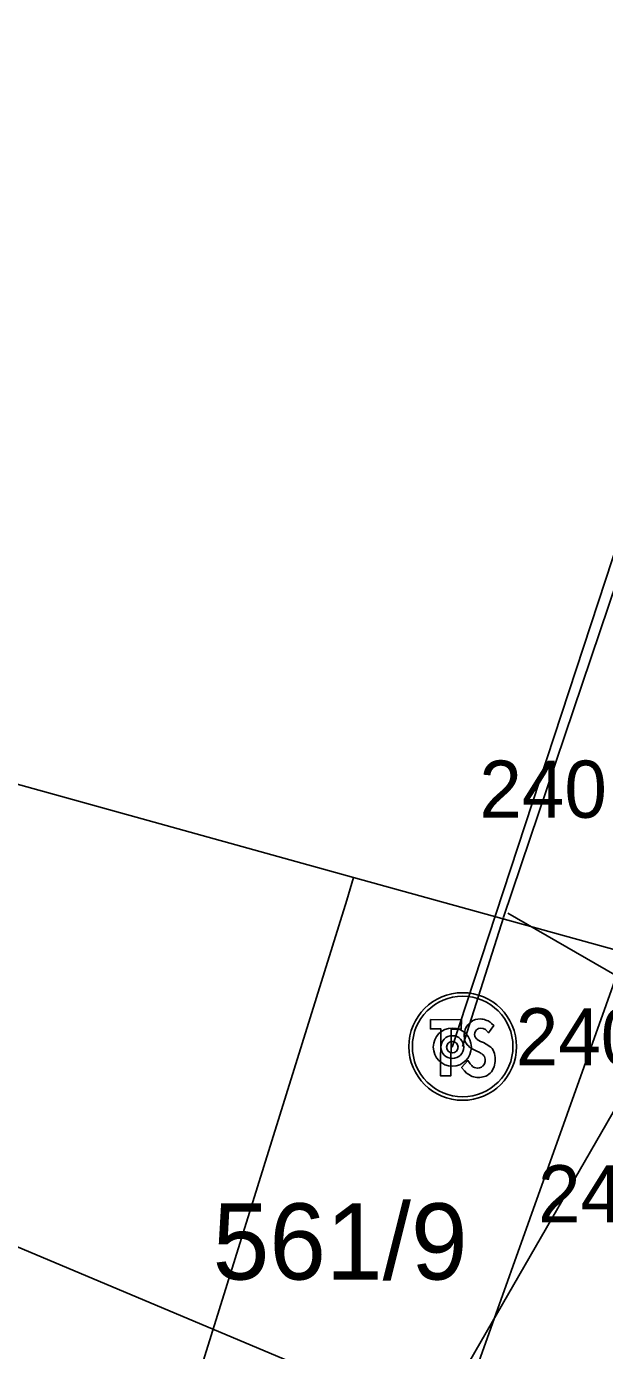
# Model space of a CAD drawing. Extents: x -555757 to -553364, y -1100723 to -1096439.
# Drawn here: x -553996.25 to -553981.08, y -1099139.41 to -1099104.66 of the extents above; entities that cross this region are included whole.
import ezdxf

# ---------------------------------------------------------------- set-up
doc = ezdxf.new("R2010")
doc.units = 0
for name, color, linetype in [('00_NÁVRH - 0.35 mm', 7, 'Continuous'), ('00_NÁVRH - Řezy', 7, 'Continuous'), ('01_HLADINA', 7, 'Continuous'), ('05_SÍTĚ - vedení VN - nadzemní', 7, 'Continuous'), ('C$SLO$PARCELY', 7, 'Continuous'), ('HRANICE$PARCELY', 7, 'Continuous'), ('PLOTY', 7, 'Continuous'), ('SLOUPY', 7, 'Continuous'), ('Stanice', 7, 'Continuous'), ('VCHOD', 7, 'Continuous'), ('VYSKA_PODR_BOD', 7, 'Continuous')]:
    doc.layers.add(name, color=color, linetype=linetype)

# ---------------------------------------------------------------- blocks, each defined once
blk = doc.blocks.new('6$01')
at = {"layer": 'SLOUPY'}
for radius in [0.5, 0.3, 0.15]:
    blk.add_circle((0, 0), radius, dxfattribs=at)
blk = doc.blocks.new('DGN_COMPLEXSHAPE')
at = {"layer": 'Stanice'}
for p, q in [((-553984.585, -1099130.792), (-553984.585, -1099130.792)), ((-553984.331, -1099130.711), (-553984.331, -1099130.711)), ((-553984.755, -1099131.19), (-553984.755, -1099131.19)), ((-553984.481, -1099131.16), (-553984.481, -1099131.16)), ((-553984.436, -1099130.998), (-553984.436, -1099130.998)), ((-553984.203, -1099130.991), (-553984.203, -1099130.991)), ((-553984.742, -1099131.264), (-553984.742, -1099131.264)), ((-553984.648, -1099131.419), (-553984.648, -1099131.419)), ((-553984.513, -1099131.515), (-553984.513, -1099131.515)), ((-553984.414, -1099131.249), (-553984.414, -1099131.249)), ((-553984.181, -1099131.371), (-553984.181, -1099131.371)), ((-553984.028, -1099131.489), (-553984.028, -1099131.489)), ((-553984.309, -1099131.615), (-553984.309, -1099131.615)), ((-553984.228, -1099131.7), (-553984.228, -1099131.7)), ((-553984.466, -1099132.24), (-553984.466, -1099132.24)), ((-553984.456, -1099131.993), (-553984.456, -1099131.993)), ((-553984.266, -1099131.946), (-553984.266, -1099131.946))]:
    blk.add_line(p, q, dxfattribs=at)
for points in [[(-553984.203, -1099130.991), (-553984.12, -1099131.075), (-553983.982, -1099130.882), (-553984.038, -1099130.829), (-553984.08, -1099130.798)], [(-553984.513, -1099131.515), (-553984.431, -1099131.559), (-553984.362, -1099131.585), (-553984.309, -1099131.615)], [(-553984.181, -1099131.371), (-553984.253, -1099131.332), (-553984.332, -1099131.299), (-553984.376, -1099131.275), (-553984.414, -1099131.249)], [(-553984.56, -1099131.935), (-553984.603, -1099131.891), (-553984.635, -1099131.834), (-553984.661, -1099131.804), (-553984.829, -1099131.982), (-553984.754, -1099132.075), (-553984.697, -1099132.131), (-553984.622, -1099132.18)]]:
    blk.add_lwpolyline(points, dxfattribs=at)
for centre, radius, start, end in [((-553984.375, -1099131.092), 0.366, 124.9121, 148.1912), ((-553984.351, -1099131.087), 0.376, 86.915, 128.4737), ((-553984.328, -1099131.057), 0.346, 66.7302, 90.4242), ((-553984.307, -1099131.093), 0.372, 52.3761, 71.9497), ((-553984.373, -1099131.148), 0.384, 170.8746, 186.3012), ((-553984.482, -1099131.182), 0.273, 181.7361, 197.6104), ((-553984.329, -1099131.13), 0.426, 147.186, 174.2063), ((-553984.31, -1099131.121), 0.176, 136.0195, 192.8606), ((-553984.295, -1099131.089), 0.199, 200.7332, 233.4744), ((-553984.316, -1099131.128), 0.178, 50.6031, 132.8388), ((-553984.474, -1099131.208), 0.274, 191.9053, 230.509), ((-553984.265, -1099131.022), 0.552, 226.0557, 243.308), ((-553984.446, -1099131.869), 0.564, 42.2209, 61.9274), ((-553984.282, -1099131.694), 0.326, 4.2129, 38.8942), ((-553984.469, -1099131.848), 0.284, 31.6483, 55.514), ((-553984.435, -1099131.794), 0.228, 318.1701, 24.4833), ((-553984.37, -1099131.836), 0.416, 301.3584, 354.7256), ((-553984.369, -1099131.774), 0.425, 346.4027, 14.1836), ((-553984.429, -1099131.912), 0.331, 234.3182, 263.5199), ((-553984.416, -1099131.799), 0.198, 223.4856, 258.3812), ((-553984.388, -1099131.724), 0.523, 261.3482, 296.5849), ((-553984.396, -1099131.826), 0.177, 250.3264, 317.6081)]:
    blk.add_arc(centre, radius, start, end, dxfattribs=at)
blk = doc.blocks.new('CEZ0035')
at = {"layer": 'Stanice'}
for p, q in [((-0.846, 0.463), (-0.844, 0.706)), ((-0.844, 0.706), (-0.034, 0.7)), ((-0.034, 0.7), (-0.036, 0.457)), ((0.468, 0.723), (0.468, 0.723)), ((-0.57, 0.461), (-0.846, 0.463)), ((-0.579, -0.772), (-0.57, 0.461)), ((-0.305, 0.459), (-0.314, -0.774)), ((-0.036, 0.457), (-0.305, 0.459)), ((0.214, 0.642), (0.214, 0.642)), ((0.363, 0.436), (0.363, 0.436)), ((0.596, 0.443), (0.596, 0.443)), ((0.596, 0.443), (0.679, 0.359)), ((0.679, 0.359), (0.817, 0.552)), ((0.761, 0.605), (0.719, 0.636)), ((0.817, 0.552), (0.761, 0.605)), ((0.044, 0.244), (0.044, 0.244)), ((0.057, 0.17), (0.057, 0.17)), ((0.151, 0.015), (0.151, 0.015)), ((0.318, 0.274), (0.318, 0.274)), ((0.423, 0.159), (0.385, 0.185)), ((0.385, 0.185), (0.385, 0.185)), ((0.467, 0.135), (0.423, 0.159)), ((0.546, 0.102), (0.467, 0.135)), ((0.618, 0.063), (0.546, 0.102)), ((0.618, 0.063), (0.618, 0.063)), ((0.286, -0.081), (0.286, -0.081)), ((0.286, -0.081), (0.368, -0.125)), ((0.368, -0.125), (0.437, -0.151)), ((0.437, -0.151), (0.49, -0.181)), ((0.49, -0.181), (0.49, -0.181)), ((0.571, -0.266), (0.571, -0.266)), ((0.771, -0.055), (0.771, -0.055)), ((0.138, -0.37), (-0.03, -0.548)), ((-0.03, -0.548), (0.045, -0.641)), ((0.045, -0.641), (0.102, -0.697)), ((0.164, -0.4), (0.138, -0.37)), ((0.196, -0.457), (0.164, -0.4)), ((0.239, -0.501), (0.196, -0.457)), ((0.343, -0.559), (0.343, -0.559)), ((0.533, -0.512), (0.533, -0.512)), ((-0.314, -0.774), (-0.579, -0.772)), ((0.102, -0.697), (0.177, -0.746)), ((0.333, -0.806), (0.333, -0.806))]:
    blk.add_line(p, q, dxfattribs=at)
blk.add_lwpolyline([(-0.844, 0.706), (-0.034, 0.7), (-0.036, 0.457), (-0.305, 0.459), (-0.314, -0.774), (-0.579, -0.772), (-0.57, 0.461), (-0.846, 0.463), (-0.844, 0.706)], dxfattribs=at)
for radius in [1.412, 1.32]:
    blk.add_circle((0, 0), radius, dxfattribs=at)
for centre, radius, start, end in [((0.448, 0.347), 0.376, 86.915, 128.4737), ((0.471, 0.377), 0.346, 66.7302, 90.4242), ((0.47, 0.304), 0.426, 147.186, 174.2063), ((0.424, 0.342), 0.366, 124.9121, 148.1912), ((0.489, 0.313), 0.176, 136.0195, 192.8606), ((0.483, 0.306), 0.178, 50.6031, 132.8388), ((0.492, 0.341), 0.372, 52.3761, 71.9497), ((0.426, 0.286), 0.384, 170.8746, 186.3012), ((0.317, 0.252), 0.273, 181.7361, 197.6104), ((0.325, 0.226), 0.274, 191.9053, 230.509), ((0.534, 0.412), 0.552, 226.0557, 243.308), ((0.504, 0.345), 0.199, 200.7332, 233.4744), ((0.353, -0.435), 0.564, 42.2209, 61.9274), ((0.33, -0.414), 0.284, 31.6483, 55.514), ((0.364, -0.36), 0.228, 318.1701, 24.4833), ((0.517, -0.26), 0.326, 4.2129, 38.8942), ((0.43, -0.34), 0.425, 346.4027, 14.1836), ((0.383, -0.365), 0.198, 223.4856, 258.3812), ((0.403, -0.392), 0.177, 250.3264, 317.6081), ((0.429, -0.402), 0.416, 301.3584, 354.7256), ((0.37, -0.478), 0.331, 234.3182, 263.5199), ((0.411, -0.29), 0.523, 261.3482, 296.5849)]:
    blk.add_arc(centre, radius, start, end, dxfattribs=at)
blk.add_blockref('DGN_COMPLEXSHAPE', (553984.799, 1099131.434), dxfattribs=at)

msp = doc.modelspace()

# ---------------------------------------------------------------- linework, layer by layer
at = {"layer": '00_NÁVRH - 0.35 mm'}
msp.add_open_spline([(-553794.11, -1099299.314), (-553795.302, -1099298.083), (-553795.885, -1099297.697), (-553798.014, -1099296.378), (-553798.648, -1099296.009), (-553799.057, -1099295.868), (-553800.013, -1099295.626), (-553800.97, -1099295.434), (-553803.916, -1099294.978), (-553807.943, -1099294.404), (-553820.006, -1099292.714), (-553824.218, -1099292.087), (-553827.541, -1099291.556), (-553834.292, -1099290.18), (-553840, -1099289.072), (-553843.606, -1099288.311), (-553846.032, -1099287.854), (-553848.004, -1099287.449), (-553849.388, -1099287.281), (-553865.944, -1099285.252), (-553871.048, -1099284.805), (-553873.856, -1099284.514), (-553874.399, -1099284.43), (-553876.775, -1099283.969), (-553879.064, -1099283.332), (-553880.051, -1099283.031), (-553881.093, -1099282.392), (-553882.188, -1099281.754), (-553883.228, -1099281.083), (-553884.328, -1099279.969), (-553885.547, -1099278.713), (-553889.777, -1099274.4), (-553901.548, -1099262.428), (-553911.972, -1099251.719), (-553924.19, -1099239.3), (-553934.53, -1099228.739), (-553940.93, -1099222.274), (-553947.073, -1099216.541), (-553953.84, -1099210.491), (-553956.731, -1099207.941), (-553957.05, -1099207.628), (-553964.746, -1099199.605), (-553968.133, -1099195.981), (-553972.842, -1099191.048), (-553973.281, -1099190.444), (-553973.656, -1099189.74), (-553976.661, -1099181.556), (-553981.28, -1099169.188), (-553982.799, -1099164.023), (-553982.956, -1099163.184), (-553982.84, -1099162.204), (-553982.616, -1099160.636), (-553981.347, -1099154.446), (-553980.688, -1099150.992), (-553979.675, -1099146.656), (-553979.439, -1099145.68), (-553978.925, -1099144.071), (-553976.623, -1099137.958), (-553971.496, -1099124.445), (-553956.509, -1099083.004), (-553948.349, -1099063.109), (-553947.145, -1099060.166), (-553946.295, -1099057.429), (-553943.525, -1099049.31), (-553939.704, -1099037.846), (-553934.366, -1099021.961), (-553930.78, -1099011.15), (-553926.744, -1098998.785), (-553924.694, -1098992.816), (-553921.255, -1098983.982), (-553917.56, -1098974.667), (-553914.06, -1098965.564), (-553908.691, -1098951.909), (-553901.821, -1098934.804), (-553901.394, -1098933.668), (-553901.099, -1098932.553), (-553900.651, -1098929.575), (-553899.921, -1098923.604), (-553898.961, -1098915.482), (-553898.391, -1098910.691), (-553898.127, -1098908.396), (-553898.218, -1098907.183), (-553898.459, -1098905.433), (-553899.12, -1098901.506), (-553900.514, -1098893.561), (-553900.636, -1098892.888), (-553900.544, -1098892.328), (-553900.228, -1098891.412), (-553899.451, -1098889.266), (-553897.423, -1098883.769), (-553893.021, -1098871.924), (-553886.932, -1098855.681), (-553885.605, -1098852.197), (-553884.629, -1098849.656), (-553884.106, -1098848.151), (-553883.861, -1098847.39), (-553883.788, -1098846.997), (-553883.77, -1098846.594), (-553883.802, -1098846.171), (-553883.858, -1098845.819), (-553884.325, -1098844.246), (-553887.679, -1098834.274), (-553890.606, -1098825.191), (-553891.018, -1098823.527), (-553891.066, -1098823.121), (-553891.005, -1098822.697), (-553890.8, -1098821.707), (-553890.203, -1098818.823), (-553888.001, -1098807.301), (-553885.789, -1098795.251), (-553885.363, -1098792.934), (-553885.23, -1098792.173), (-553885.147, -1098791.711), (-553885.147, -1098791.302), (-553885.151, -1098791.006), (-553885.22, -1098790.609), (-553886.502, -1098784.837), (-553888.275, -1098776.483), (-553889.523, -1098771.371), (-553889.704, -1098770.489), (-553889.76, -1098769.236), (-553890.011, -1098761.77), (-553890.328, -1098747.9), (-553890.415, -1098743.459), (-553890.422, -1098742.114), (-553890.412, -1098741.338), (-553890.227, -1098740.638), (-553887.44, -1098731.802), (-553883.473, -1098718.833), (-553877.882, -1098700.91), (-553873.654, -1098687.07), (-553869.067, -1098673.807), (-553863.431, -1098657.948), (-553859.616, -1098647.384), (-553854.518, -1098632.992), (-553853.778, -1098630.91), (-553852.903, -1098628.215), (-553851.147, -1098622.78), (-553848.209, -1098613.648), (-553844.194, -1098601.116), (-553841.044, -1098590.723), (-553837.173, -1098577.952), (-553835.011, -1098570.679), (-553833.035, -1098564.139), (-553830.71, -1098556.281), (-553828.586, -1098548.945), (-553827.55, -1098545.495), (-553827.333, -1098544.629), (-553827.114, -1098543.601), (-553826.943, -1098542.73), (-553826.694, -1098541.466), (-553826.528, -1098540.348), (-553825.375, -1098531.946), (-553823.552, -1098519.221), (-553822.413, -1098510.953), (-553821.269, -1098503.56), (-553820.357, -1098496.716), (-553819.264, -1098489.108), (-553818.909, -1098486.041), (-553818.853, -1098485.532), (-553818.848, -1098485.156), (-553818.852, -1098484.16), (-553818.788, -1098477.885), (-553818.638, -1098467.214), (-553818.464, -1098454.698), (-553818.096, -1098433.157), (-553817.825, -1098416.015), (-553817.758, -1098409.125), (-553817.716, -1098406.971), (-553817.481, -1098400.257), (-553817.113, -1098388.412), (-553816.885, -1098378.571), (-553816.924, -1098376.341), (-553817.085, -1098375.505), (-553817.655, -1098372.671), (-553823.7, -1098343.15), (-553824.052, -1098341.595), (-553824.653, -1098340.008), (-553827.064, -1098334.584), (-553831.231, -1098324.895), (-553836.053, -1098314.241), (-553837.067, -1098312.263), (-553794.638, -1099298.639), (-553836.551, -1098313.247)], degree=3, dxfattribs=at)
at = {"layer": '00_NÁVRH - Řezy'}
msp.add_line((-554002.421, -1099134.2), (-553949.342, -1099156.5), dxfattribs=at)
at = {"layer": '01_HLADINA'}
msp.add_open_spline([(-553982.932, -1099162.753), (-553982.908, -1099162.57), (-553982.768, -1099161.862), (-553982.46, -1099159.072), (-553981.456, -1099155.374), (-553980.684, -1099150.675), (-553979.927, -1099147.778), (-553979.401, -1099145.454), (-553978.408, -1099142.539), (-553975.658, -1099135.502), (-553967.928, -1099115.239), (-553959.517, -1099089.9), (-553950.852, -1099068.8), (-553947.577, -1099061.346), (-553947.246, -1099060.445)], degree=3, dxfattribs=at)
at = {"layer": '05_SÍTĚ - vedení VN - nadzemní'}
for points in [[(-553966.04, -1099075.63), (-553983.723, -1099128.039)], [(-553983.725, -1099128.044), (-553984.799, -1099131.434)]]:
    msp.add_lwpolyline(points, dxfattribs=at)
at = {"layer": 'HRANICE$PARCELY'}
for p, q in [((-554009.27, -1099121), (-553987.66, -1099127)), ((-553980.54, -1099128.97), (-553987.66, -1099127)), ((-553980.54, -1099128.97), (-553986.33, -1099145.17))]:
    msp.add_line(p, q, dxfattribs=at)
msp.add_lwpolyline([(-553987.66, -1099127), (-553987.84, -1099127.59), (-553992.36, -1099142.11), (-553986.33, -1099145.17)], dxfattribs=at)
at = {"layer": 'PLOTY'}
for p, q in [((-553983.612, -1099127.933), (-553979.28, -1099130.43)), ((-553979.28, -1099130.43), (-553987.39, -1099144.5))]:
    msp.add_line(p, q, dxfattribs=at)
at = {"layer": 'VCHOD'}
msp.add_line((-553985.07, -1099131.45), (-553966.67, -1099075.3), dxfattribs=at)

# ---------------------------------------------------------------- block references
msp.add_blockref('CEZ0035', (-553984.799, -1099131.434))
msp.add_blockref('6$01', (-553985.07, -1099131.45), dxfattribs=at)

# ---------------------------------------------------------------- texts
at = {"layer": 'C$SLO$PARCELY'}
msp.add_text('561/9', height=2, dxfattribs=at).set_placement((-553991.361, -1099137.55))
at = {"layer": 'VYSKA_PODR_BOD'}
for s, p in [('240.44', (-553984.36, -1099125.43)), ('240.41', (-553983.405, -1099131.93)), ('240.47', (-553982.82, -1099136.05))]:
    msp.add_text(s, height=1.5, dxfattribs=at).set_placement(p)

doc.saveas('drawing.dxf')
